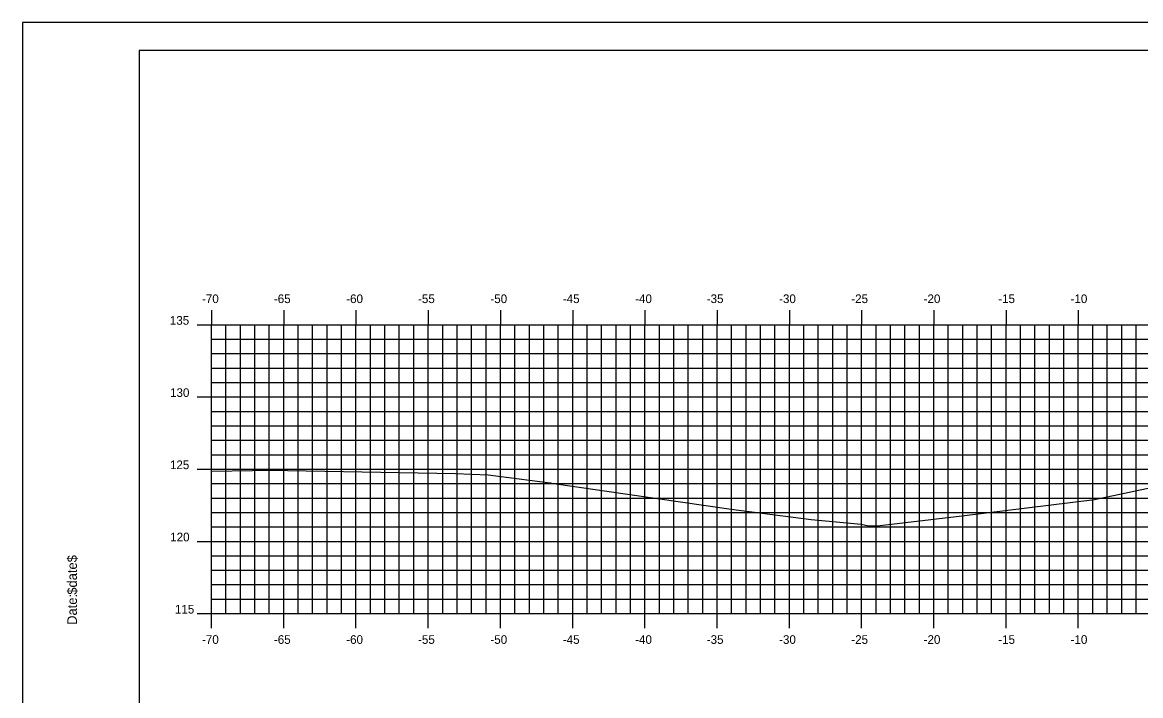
# Model space of a CAD drawing. Extents: x 851960 to 852132, y 365624 to 365734.
# Drawn here: x 851960.2 to 852037.6, y 365687.3 to 365734 of the extents above; entities that cross this region are included whole.
import ezdxf

# ---------------------------------------------------------------- set-up
doc = ezdxf.new("R2010")
doc.units = 0
for name, color, linetype in [('BORDER', 7, 'Continuous'), ('H_V ANNOTATION', 7, 'Continuous'), ('M_Roadway_Centerline', 7, 'Continuous'), ('MAJOR', 7, 'Continuous'), ('MINOR', 7, 'Continuous'), ('PLOT BOUNDARY', 7, 'Continuous'), ('S_Roadway_Centerline', 7, 'Continuous')]:
    doc.layers.add(name, color=color, linetype=linetype)

msp = doc.modelspace()

# ---------------------------------------------------------------- linework, layer by layer
at = {"layer": 'BORDER'}
msp.add_lwpolyline([(851968.279, 365627.027), (852128.279, 365627.027), (852128.279, 365732.027), (851968.279, 365732.027)], close=True, dxfattribs=at)
at = {"layer": 'MAJOR'}
for p, q in [((851973.279, 365714.029), (851973.279, 365713.027)), ((851978.279, 365714.029), (851978.279, 365713.027)), ((851983.279, 365714.029), (851983.279, 365713.027)), ((851988.279, 365714.029), (851988.279, 365713.027)), ((851993.279, 365714.029), (851993.279, 365713.027)), ((851998.279, 365714.029), (851998.279, 365713.027)), ((852003.279, 365714.029), (852003.279, 365713.027)), ((852008.279, 365714.029), (852008.279, 365713.027)), ((852013.279, 365714.029), (852013.279, 365713.027)), ((852018.279, 365714.029), (852018.279, 365713.027)), ((852023.279, 365714.029), (852023.279, 365713.027)), ((852028.279, 365714.029), (852028.279, 365713.027)), ((852033.279, 365714.029), (852033.279, 365713.027)), ((851972.277, 365713.027), (851973.279, 365713.027)), ((851973.279, 365713.027), (852113.279, 365713.027)), ((851973.279, 365693.027), (851973.279, 365713.027)), ((851973.279, 365693.027), (851973.279, 365713.027)), ((851973.279, 365713.027), (852113.279, 365713.027)), ((851978.279, 365693.027), (851978.279, 365713.027)), ((851983.279, 365693.027), (851983.279, 365713.027)), ((851988.279, 365693.027), (851988.279, 365713.027)), ((851993.279, 365693.027), (851993.279, 365713.027)), ((851998.279, 365693.027), (851998.279, 365713.027)), ((852003.279, 365693.027), (852003.279, 365713.027)), ((852008.279, 365693.027), (852008.279, 365713.027)), ((852013.279, 365693.027), (852013.279, 365713.027)), ((852018.279, 365693.027), (852018.279, 365713.027)), ((852023.279, 365693.027), (852023.279, 365713.027)), ((852028.279, 365693.027), (852028.279, 365713.027)), ((852033.279, 365693.027), (852033.279, 365713.027)), ((851972.277, 365708.027), (851973.279, 365708.027)), ((851973.279, 365708.027), (852113.279, 365708.027)), ((851972.277, 365703.027), (851973.279, 365703.027)), ((851973.279, 365703.027), (852113.279, 365703.027)), ((851972.277, 365698.027), (851973.279, 365698.027)), ((851973.279, 365698.027), (852113.279, 365698.027)), ((851972.277, 365693.027), (851973.279, 365693.027)), ((851973.279, 365693.027), (852113.279, 365693.027)), ((851973.279, 365693.027), (852113.279, 365693.027)), ((851973.279, 365692.025), (851973.279, 365693.027)), ((851978.279, 365692.025), (851978.279, 365693.027)), ((851983.279, 365692.025), (851983.279, 365693.027)), ((851988.279, 365692.025), (851988.279, 365693.027)), ((851993.279, 365692.025), (851993.279, 365693.027)), ((851998.279, 365692.025), (851998.279, 365693.027)), ((852003.279, 365692.025), (852003.279, 365693.027)), ((852008.279, 365692.025), (852008.279, 365693.027)), ((852013.279, 365692.025), (852013.279, 365693.027)), ((852018.279, 365692.025), (852018.279, 365693.027)), ((852023.279, 365692.025), (852023.279, 365693.027)), ((852028.279, 365692.025), (852028.279, 365693.027)), ((852033.279, 365692.025), (852033.279, 365693.027))]:
    msp.add_line(p, q, dxfattribs=at)
at = {"layer": 'MINOR'}
for p, q in [((851974.279, 365693.027), (851974.279, 365713.027)), ((851975.279, 365693.027), (851975.279, 365713.027)), ((851976.279, 365693.027), (851976.279, 365713.027)), ((851977.279, 365693.027), (851977.279, 365713.027)), ((851979.279, 365693.027), (851979.279, 365713.027)), ((851980.279, 365693.027), (851980.279, 365713.027)), ((851981.279, 365693.027), (851981.279, 365713.027)), ((851982.279, 365693.027), (851982.279, 365713.027)), ((851984.279, 365693.027), (851984.279, 365713.027)), ((851985.279, 365693.027), (851985.279, 365713.027)), ((851986.279, 365693.027), (851986.279, 365713.027)), ((851987.279, 365693.027), (851987.279, 365713.027)), ((851989.279, 365693.027), (851989.279, 365713.027)), ((851990.279, 365693.027), (851990.279, 365713.027)), ((851991.279, 365693.027), (851991.279, 365713.027)), ((851992.279, 365693.027), (851992.279, 365713.027)), ((851994.279, 365693.027), (851994.279, 365713.027)), ((851995.279, 365693.027), (851995.279, 365713.027)), ((851996.279, 365693.027), (851996.279, 365713.027)), ((851997.279, 365693.027), (851997.279, 365713.027)), ((851999.279, 365693.027), (851999.279, 365713.027)), ((852000.279, 365693.027), (852000.279, 365713.027)), ((852001.279, 365693.027), (852001.279, 365713.027)), ((852002.279, 365693.027), (852002.279, 365713.027)), ((852004.279, 365693.027), (852004.279, 365713.027)), ((852005.279, 365693.027), (852005.279, 365713.027)), ((852006.279, 365693.027), (852006.279, 365713.027)), ((852007.279, 365693.027), (852007.279, 365713.027)), ((852009.279, 365693.027), (852009.279, 365713.027)), ((852010.279, 365693.027), (852010.279, 365713.027)), ((852011.279, 365693.027), (852011.279, 365713.027)), ((852012.279, 365693.027), (852012.279, 365713.027)), ((852014.279, 365693.027), (852014.279, 365713.027)), ((852015.279, 365693.027), (852015.279, 365713.027)), ((852016.279, 365693.027), (852016.279, 365713.027)), ((852017.279, 365693.027), (852017.279, 365713.027)), ((852019.279, 365693.027), (852019.279, 365713.027)), ((852020.279, 365693.027), (852020.279, 365713.027)), ((852021.279, 365693.027), (852021.279, 365713.027)), ((852022.279, 365693.027), (852022.279, 365713.027)), ((852024.279, 365693.027), (852024.279, 365713.027)), ((852025.279, 365693.027), (852025.279, 365713.027)), ((852026.279, 365693.027), (852026.279, 365713.027)), ((852027.279, 365693.027), (852027.279, 365713.027)), ((852029.279, 365693.027), (852029.279, 365713.027)), ((852030.279, 365693.027), (852030.279, 365713.027)), ((852031.279, 365693.027), (852031.279, 365713.027)), ((852032.279, 365693.027), (852032.279, 365713.027)), ((852034.279, 365693.027), (852034.279, 365713.027)), ((852035.279, 365693.027), (852035.279, 365713.027)), ((852036.279, 365693.027), (852036.279, 365713.027)), ((852037.279, 365693.027), (852037.279, 365713.027)), ((851973.279, 365712.027), (852113.279, 365712.027)), ((851973.279, 365712.027), (851974.281, 365712.027)), ((851973.279, 365711.027), (852113.279, 365711.027)), ((851973.279, 365711.027), (851974.281, 365711.027)), ((851973.279, 365710.027), (852113.279, 365710.027)), ((851973.279, 365710.027), (851974.281, 365710.027)), ((851973.279, 365709.027), (852113.279, 365709.027)), ((851973.279, 365709.027), (851974.281, 365709.027)), ((851973.279, 365707.027), (852113.279, 365707.027)), ((851973.279, 365707.027), (851974.281, 365707.027)), ((851973.279, 365706.027), (852113.279, 365706.027)), ((851973.279, 365706.027), (851974.281, 365706.027)), ((851973.279, 365705.027), (852113.279, 365705.027)), ((851973.279, 365705.027), (851974.281, 365705.027)), ((851973.279, 365704.027), (852113.279, 365704.027)), ((851973.279, 365704.027), (851974.281, 365704.027)), ((851973.279, 365702.027), (852113.279, 365702.027)), ((851973.279, 365702.027), (851974.281, 365702.027)), ((851973.279, 365701.027), (852113.279, 365701.027)), ((851973.279, 365701.027), (851974.281, 365701.027)), ((851973.279, 365700.027), (852113.279, 365700.027)), ((851973.279, 365700.027), (851974.281, 365700.027)), ((851973.279, 365699.027), (852113.279, 365699.027)), ((851973.279, 365699.027), (851974.281, 365699.027)), ((851973.279, 365697.027), (852113.279, 365697.027)), ((851973.279, 365697.027), (851974.281, 365697.027)), ((851973.279, 365696.027), (852113.279, 365696.027)), ((851973.279, 365696.027), (851974.281, 365696.027)), ((851973.279, 365695.027), (852113.279, 365695.027)), ((851973.279, 365695.027), (851974.281, 365695.027)), ((851973.279, 365694.027), (852113.279, 365694.027)), ((851973.279, 365694.027), (851974.281, 365694.027))]:
    msp.add_line(p, q, dxfattribs=at)
at = {"layer": 'PLOT BOUNDARY'}
msp.add_lwpolyline([(851960.186, 365623.968), (852130.186, 365623.968), (852130.186, 365733.968), (851960.186, 365733.968)], close=True, dxfattribs=at)
at = {"layer": 'S_Roadway_Centerline'}
msp.add_lwpolyline([(851973.279, 365702.877), (851976.108, 365702.942), (851976.899, 365702.961), (851976.987, 365702.962), (851976.991, 365702.962), (851977.103, 365702.96), (851977.257, 365702.956), (851990.166, 365702.721), (851992.428, 365702.638), (851996.727, 365702.072), (851996.741, 365702.071), (851996.805, 365702.061), (852009.26, 365700.253), (852014.78, 365699.534), (852018.236, 365699.212), (852018.756, 365699.103), (852019.554, 365699.126), (852025.212, 365699.783), (852034.395, 365700.928), (852038.877, 365701.862)], dxfattribs=at)

# ---------------------------------------------------------------- texts
at = {"layer": 'BORDER'}
for s, p in [('$date$', (851963.964, 365694.332)), ('Date:', (851963.964, 365692.244))]:
    msp.add_text(s, height=0.6696, rotation=90, dxfattribs=at).set_placement(p)
at = {"layer": 'H_V ANNOTATION'}
for s, p in [('-70', (851972.62, 365714.527)), ('-65', (851977.596, 365714.527)), ('-60', (851982.604, 365714.527)), ('-55', (851987.575, 365714.527)), ('-50', (851992.583, 365714.527)), ('-45', (851997.596, 365714.527)), ('-40', (852002.604, 365714.527)), ('-35', (852007.559, 365714.527)), ('-30', (852012.567, 365714.527)), ('-25', (852017.564, 365714.527)), ('-20', (852022.572, 365714.527)), ('-15', (852027.736, 365714.527)), ('-10', (852032.744, 365714.527)), ('135', (851970.393, 365713.027)), ('130', (851970.409, 365708.027)), ('125', (851970.403, 365703.027)), ('120', (851970.419, 365698.027)), ('115', (851970.746, 365693.027)), ('-70', (851972.62, 365690.927)), ('-65', (851977.596, 365690.927)), ('-60', (851982.604, 365690.927)), ('-55', (851987.575, 365690.927)), ('-50', (851992.583, 365690.927)), ('-45', (851997.596, 365690.927)), ('-40', (852002.604, 365690.927)), ('-35', (852007.559, 365690.927)), ('-30', (852012.567, 365690.927)), ('-25', (852017.564, 365690.927)), ('-20', (852022.572, 365690.927)), ('-15', (852027.736, 365690.927)), ('-10', (852032.744, 365690.927))]:
    msp.add_text(s, height=0.6, dxfattribs=at).set_placement(p)
at = {"layer": 'M_Roadway_Centerline'}
for s, p in [('C', (851976.981, 365702.962)), ('L', (851976.987, 365702.955))]:
    msp.add_text(s, height=0.0146, dxfattribs=at).set_placement(p)
at = {"layer": 'MAJOR'}
msp.add_text('-', height=0.006, dxfattribs=at).set_placement((851973.274, 365693.027))

doc.saveas('drawing.dxf')
